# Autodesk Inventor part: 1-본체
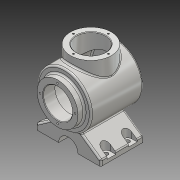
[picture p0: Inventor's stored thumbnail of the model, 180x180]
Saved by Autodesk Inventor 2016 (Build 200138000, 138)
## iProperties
Created: 2017-04
Part Number: 1-본체
Material: 알루미늄 6061
Document SubType Name: Modeling
Designer: H
Density: 2.7 g/cm^3
Appearance: 알루미늄 - 평지
Mass: 1664.52 g
Surface Area: 1066.89 cm^2
Volume: 616.49 cm^3
Author: H
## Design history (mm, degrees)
sketch "스케치1"
  geometry: L1 (-50, 0)-(46.336, 0); L2 (46.336, 0)-(46.336, 50); L3 (46.336, 50)-(-50, 50); L4 (-50, 50)-(-50, 0); L5 (-50, 0)-(-62, 0); L6 (-62, 0)-(-62, 38); L7 (-62, 38)-(-50, 38); L8 (-50, 38)-(-50, 0); L9 (46.336, 0)-(58, 0); A1 r 113 centre (-55, 0) between (58, 0) and (46.336, 50); 1 further point
  constraints: 18 end point, 4 parallel, 3 horizontal, 2 perpendicular, 2 point on circle, 2 point on line, 1 centre point
  dimensions: "d0" = 50 distance from line of point (0, 0) L4; "d1" = 108 distance of L9.end L1.start; "d2" = 12 distance between parallel lines of L4 L6; "d3" = 76 diameter of L7 L5; "d4" = 100 diameter of L3 L1; "d5" = 113 radius of A1
revolve "회전1" sketch "스케치1" stored, may be unused: angle "d6" = 90 deg
sketch "스케치2"
  geometry: C1 r 38 at (0, 0); 1 further point
  constraints: 1 centre point, 1 coincident
  dimensions: "d7" = 76 diameter of C1
extrude "돌출1" join sketch "스케치2" distance "d8" = 65; taper "d9" = 0 deg
sketch "스케치3"
  geometry: L1 (-50, 50)-(46.336, 50) reference; L2 (-50, -50)-(46.336, -50) reference; L3 (-50, -50)-(-50, 50) reference; L4 (39.916, 40)-(-40, 40); L5 (-40, 40)-(-40, 0); L6 (-40, 0)-(48, 0); A1 r 113 centre (-55, 0) between (46.336, -50) and (46.336, 50) reference; A2 r 103 centre (-55, 0) between (48, 0) and (39.916, 40); 1 further point
  constraints: 6 end point, 2 point on circle, 1 centre point, 1 horizontal, 1 point on line, 1 other
  dimensions: "d10" = 10 radial gap between concentric circles of A1 A2; "d11" = 10 distance between parallel lines of L5 L3
revolve "회전2" sketch "스케치3" stored, may be unused: angle "d12" = 90 deg
hole "구멍1" diameter "d15" = 54; stored, may be unused: countersink angle "d19" = 90 deg, drill point angle "d21" = 118 deg; dims "d13" = 10, "d14" = 10, "d16" = 6, "d17" = 4, "d18" = 2, "d20" = 22
hole "구멍2" diameter "d24" = 54; stored, may be unused: countersink angle "d28" = 90 deg, drill point angle "d30" = 118 deg; dims "d22" = 10, "d23" = 10, "d25" = 6, "d26" = 4, "d27" = 2, "d29" = 22
node "작업 평면2"
sketch "스케치5"
  geometry: L1 (60, -72)-(-60, -72); L2 (-60, -72)-(-60, -82); L3 (-60, -82)-(60, -82); L4 (60, -82)-(60, -72); 2 further points
  constraints: 8 end point, 2 parallel, 1 horizontal, 1 midpoint, 1 perpendicular, 1 vertical alignment
  dimensions: "d38" = 10 distance of L1.end L2.end; "d39" = 82 distance from line of L3 point (0, 0); "d40" = 120 distance of L2.end L3.end
extrude "돌출3" join sketch "스케치5" distance "d41" = 80; taper "d42" = 0 deg
sketch "스케치6"
  geometry: L1 (-60, -72)-(60, -72) reference; L2 (-60, -72)-(-21.584, -45.101); L3 (-60, -82)-(-60, -72) reference; L4 (60, -72)-(21.584, -45.101); L5 (60, -72)-(60, -82) reference; A1 r 50 centre (0, 0) between (-21.584, -45.101) and (21.584, -45.101) reference; 1 further point
  constraints: 4 end point, 2 point on circle
  dimensions: "d43" = 55 deg angle of L3 L2; "d44" = 55 deg angle of L5 L4 (= d43)
extrude "돌출4" join sketch "스케치6" distance "d45" = 80; taper "d46" = 0 deg
sketch "스케치7"
  geometry: L1 (60, -82)-(-60, -82) reference; C1 r 18 at (0, -82); 2 further points
  constraints: 1 centre point, 1 coincident, 1 midpoint
  dimensions: "d48" = 18 radius of C1
extrude "돌출5" cut sketch "스케치7" stored distance "d49" = 80; taper "d50" = 0 deg
node "작업 평면4"
sketch "스케치9"
  geometry: L1 (0, 0)-(0, 80) reference; L2 (10, 60)-(0, 60); L3 (10, 68)-(0, 68); L4 (0, 52)-(10, 52); L5 (10, 20)-(0, 20); L6 (10, 28)-(0, 28); L7 (0, 12)-(10, 12); L8 (120, 0)-(120, 80) reference; L9 (110, 60)-(120, 60); L10 (110, 52)-(120, 52); L11 (120, 68)-(110, 68); L12 (110, 20)-(120, 20); L13 (110, 12)-(120, 12); L14 (120, 28)-(110, 28); L15 (110, 20)-(10, 20); L16 (10, 20)-(10, 60); L17 (10, 60)-(110, 60); L18 (110, 60)-(110, 20); L19 (78, 0)-(120, 0) reference; A1 r 8 centre (10, 60) between (10, 52) and (10, 68); A2 r 8 centre (0, 60) between (0, 68) and (0, 52); A3 r 8 centre (10, 20) between (10, 12) and (10, 28); A4 r 8 centre (0, 20) between (0, 28) and (0, 12); A5 r 8 centre (110, 60) between (110, 68) and (110, 52); A6 r 8 centre (120, 60) between (120, 52) and (120, 68); A7 r 8 centre (110, 20) between (110, 28) and (110, 12); A8 r 8 centre (120, 20) between (120, 12) and (120, 28); 6 further points
  constraints: 40 end point, 16 point on circle, 16 tangent, 8 centre point, 6 parallel, 5 midpoint, 5 perpendicular, 4 point on line, 1 horizontal, 1 vertical alignment
  dimensions: "d55" = 8 radius of A1; "d56" = 8 radius of A5 (= d55); "d57" = 8 radius of A7 (= d55); "d58" = 8 radius of A3 (= d55); "d109" = 40 distance of L5.start L2.start; "d110" = 100 distance of L12.start L5.start; "d111" = 20 distance between parallel lines of L19 L15
extrude "돌출6" cut sketch "스케치9" distance "d59" = 30; taper "d60" = 0 deg
fillet "모깎기1" dims "d61" = 3
fillet "모깎기2" dims "d62" = 3
fillet "모깎기3" dims "d63" = 3
fillet "모깎기4" dims "d64" = 3
fillet "모깎기5" dims "d65" = 3
chamfer "모따기1" distance "d66" = 1; stored, may be unused: second distance "d67" = 2, angle "d68" = 45 deg
sketch "스케치10" dims "d69" = 65
  geometry: L1 (0, 0)-(0, 32.5); 1 further point
  constraints: 2 end point, 1 coincident, 1 vertical, 1 vertical alignment, 2 other
hole "구멍3" sketch "스케치10" at (0, 32.5) diameter "d70" = 3.242; stored, may be unused: countersink angle "d74" = 90 deg, drill point angle "d76" = 118 deg; dims "d71" = 8, "d72" = 4, "d73" = 2, "d75" = 10
sketch "스케치11" dims "d80" = 65
  geometry: L1 (0, 0)-(-32.5, 0); 1 further point
  constraints: 2 end point, 1 coincident, 1 horizontal, 1 horizontal alignment, 2 other
hole "구멍4" sketch "스케치11" at (-32.5, 0) diameter "d81" = 3.242; stored, may be unused: countersink angle "d85" = 90 deg, drill point angle "d87" = 118 deg; dims "d82" = 8, "d83" = 4, "d84" = 2, "d86" = 10
node "작업 평면5"
sketch "스케치12"
  geometry: 2 further points
  constraints: 1 coincident, 1 other
feature "엠보싱1" sketch "스케치12" dims "d0" = 50, "d1" = 108, "d2" = 12, "d3" = 76, "d4" = 100, "d5" = 113, "d91" = 0.5, "d92" = 0
hole "구멍5" diameter "d95" = 8; stored, may be unused: countersink angle "d99" = 90 deg, drill point angle "d101" = 118 deg; dims "d93" = 10, "d94" = 10, "d96" = 8, "d97" = 4, "d98" = 2, "d100" = 10
fillet "모깎기6" dims "d108" = 3
node "솔리드1"
pattern_circular "원형 패턴1" dims angle "d78" = 360 deg
pattern_circular "원형 패턴2" dims angle "d89" = 360 deg
pattern_linear "직사각형 패턴1" dims "d104" = 40
other parameters: "d37" = -42, "d52" = -6
